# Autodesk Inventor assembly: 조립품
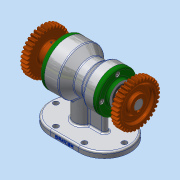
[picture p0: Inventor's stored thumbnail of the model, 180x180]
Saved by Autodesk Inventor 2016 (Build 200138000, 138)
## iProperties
Created: 2020-01
Part Number: 조립품
Document SubType Name: Assembly
Designer: woori
Author: woori
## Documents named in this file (13)
- C:\Users\woori\Desktop\700104v1001\답안조립품.iam
- C:\Users\woori\Desktop\700104v1001\본체.ipt
- C:\Users\woori\Desktop\700104v1001\뒤커버.ipt
- C:\Users\woori\Desktop\700104v1001\멈춤나사 M3.ipt
- C:\Users\woori\Desktop\700104v1001\베어링 6203.ipt
- C:\Users\woori\Desktop\700104v1001\베어링 6205.ipt
- C:\Users\woori\Desktop\700104v1001\볼트 M4.ipt
- C:\Users\woori\Desktop\700104v1001\앞커버.ipt
- C:\Users\woori\Desktop\700104v1001\스퍼기어.ipt
- C:\Users\woori\Desktop\700104v1001\오일 실 17 30 8.ipt
- C:\Users\woori\Desktop\700104v1001\오일 실 25 38 8.ipt
- C:\Users\woori\Desktop\700104v1001\축.ipt
- C:\Users\woori\Desktop\700104v1001\키 5 x 5 x 18.ipt
